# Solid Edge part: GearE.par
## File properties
Author: Chalangana Oshan
Template: iso metric part.par
Last saved by: Nimesh.N
Revision: 17
Application: Solid Edge
Density: 7250.000 kg/m^3
Accuracy: 0.990
Username: Nimesh.N
Material: Iron:0.6015 , EN-GJL-150
Face Style: Gray
Fill Style: ANSI31(Iron)
Grouping: Iron\Gray Cast Iron
LibraryName: Materials-DIN
Coef. of Thermal Exp: 1.05e-05
Thermal Conductivity: 58.0
Specific Heat: 460.0
Modulus of Elasticity: 80000000000.0
Poisson's Ratio: 0.26
Yield Stress: 100593984.0
Ultimate Stress: 150825984.0
Elongation: 0.0
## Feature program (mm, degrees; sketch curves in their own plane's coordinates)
sketch for "unnamed Protrusion 1" plane through (0, 0, 0) normal (0, 0, 1) x-axis (1, 0, 0)
  circle centre (0, 0) radius 90
extrude "unnamed Protrusion 1" add finite 130 along -normal
sketch used by "unnamed Cutout 1" plane through (0, 0, 0) normal (0, 0, 1) x-axis (1, 0, 0)
  line (0, 0) -> (-17.5581, 88.2707)
  line (0, 0) -> (-14.6606, 88.7979)
  line (0, 0) -> (-15.6283, 88.6327)
  line (-3.3121, 67.4187) -> (3.3121, 67.4187)
  arc centre (-60.8934, 50.5549) radius 60 from (-14.6606, 88.7979) to (-3.3121, 67.4187) cw
  arc centre (60.8934, 50.5549) radius 60 from (14.6606, 88.7979) to (3.3121, 67.4187) ccw
extrude "unnamed Cutout 1" cut through along -normal
pattern "unnamed Pattern 1" of "unnamed Cutout 1"
pattern "unnamed Pattern 2"
sketch for "unnamed Cutout 2" plane through (0, 0, 0) normal (0, 0, 1) x-axis (0.707107, 0.707107, 0)
extrude "unnamed Cutout 2" cut through along -normal
sketch for "unnamed Cutout 3" plane through (0, 0, 0) normal (0, 0, 1) x-axis (0.707107, 0.707107, 0)
extrude "unnamed Cutout 3" cut through along -normal
Other named dimensions: "ExtrudedSurface_3": FiniteDepth = 130 mm
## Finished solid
Body 1: sheet body, 1 face, 2 edges, 0 vertices.
  Faces by surface: cylinder 1
  Edges by curve: circle 2
Body 2: solid body, 70 faces, 204 edges, 136 vertices.
  Faces by surface: cylinder 49, plane 21
  Edges by curve: line 106, circle 98
Bounding box of the edges (mm): 177.596 x 177.596 x 130.000, from (-88.7979, -88.7979, -130) to (88.7979, 88.7979, 0).
Cylindrical faces by radius (mm): R34.03 x1, R60 x32, R80 x1, R90 x16
Planar faces by outward normal: +x 1, +y 1, +z 1, -x 1, -y 1, -z 1, oblique 15
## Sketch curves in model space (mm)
line (0, 0, 0) -> (-15.6283, 88.6327, 0)
line (0, 0, 0) -> (-17.5581, 88.2707, 0)
line (0, 0, 0) -> (4.4161, 89.8916, 0)
line (0, 0, 0) -> (-4.4161, 89.8916, 0)
arc centre (60.8934, 50.5549, 0) radius 60 from (14.6606, 88.7979, 0) through (7.8971, 78.6865, 0) to (3.3121, 67.4187, 0)
line (-3.3121, 67.4187, 0) -> (3.3121, 67.4187, 0)
arc centre (-60.8934, 50.5549, 0) radius 60 from (-14.6606, 88.7979, 0) through (-7.8971, 78.6865, 0) to (-3.3121, 67.4187, 0)
line (0, 0, 0) -> (-14.6606, 88.7979, 0)
circle centre (0, 0, 0) radius 90
circle centre (0, 0, 0) radius 80
circle centre (0, 0, 0) radius 67.5
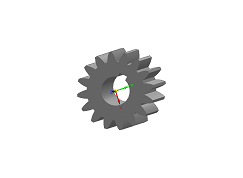
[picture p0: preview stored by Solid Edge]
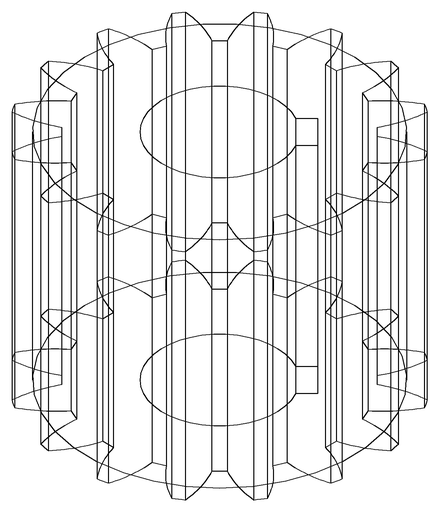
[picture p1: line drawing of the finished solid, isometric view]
